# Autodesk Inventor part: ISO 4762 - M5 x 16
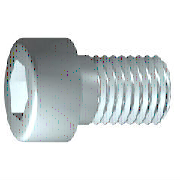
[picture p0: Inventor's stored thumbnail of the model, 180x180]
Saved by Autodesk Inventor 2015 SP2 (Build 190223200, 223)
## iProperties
Created: 2012-02
Part Number: ISO 4762 - M5 x 16
Material: Edelstahl, 440C
Description: Innensechskantschraube
Document SubType Name: Modeling
Standard: ISO 4762
Designer: Dan
Standard Revision: 1998
Standards Organization: DIN
Language: de-DE
Size Designation: M5 x 16
Categories: <MemberInstance><Categories><Category DisplayName="Verbindungselemente" InternalName="e4da775c-781d-43d5-af7c-5136215cf5a6" Mnemonic="FSTN"><Category DisplayNam
Density: 7.75 g/cm^3
Appearance: Halbpoliert
IsCustomPart: 0
Author: Dan
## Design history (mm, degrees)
sketch "Skizze1"
  geometry: L1 (-1.167, 0)-(16, 0); L2 (16, 0)-(16, 2.5); L3 (16, 2.5)-(2, 2.5); L4 (2, 2.5)-(1.509, 2.5); L5 (1.509, 2.5)-(0, 2.5); L6 (0, 2.5)-(0, 4.25); L7 (0, 4.25)-(-5, 4.25); L8 (-5, 4.25)-(-5, 2.309); L9 (-5, 2.309)-(-2.5, 2.309); L10 (-2.5, 2.309)-(-1.167, 0); L11 (-9.2, 0)-(20.2, 0) reference; L12 (0, -0.85)-(0, 5.1) reference; L13 (2, 2.5)-(0, 2.5)
  constraints: 22 end point, 6 parallel, 2 collinear, 2 perpendicular, 1 horizontal, 1 point on line
  dimensions: "d1" = 14 distance from line of L3.end L2 (= GEL); "d2" = 0.49086 distance of L4.end L3.end (computed from GAL); "d3" = 5 distance between parallel lines of L8 L6 (= KOH); "d4" = 2.5 distance of L8.end L9.end (= INTI); "d5" = 60 deg angle of L10 L1; "d6" = 5 diameter of L3 L1 (= GD); "d7" = 5 diameter of L5 L1 (= BDM); "d8" = 4.6188 diameter of L9 L1 (= 1.1547 x SW); "d9" = 8.5 diameter of L7 L1 (= KOD); "d26" = 16 distance between parallel lines of L12 L2 (= NLG)
revolve "Körper" sketch "Skizze1" stored, may be unused: angle "d10" = 90 deg
sketch "Skizze2"
  geometry: L1 (0, -5.95)-(0, 5.95) reference; L2 (-5.95, 0)-(5.95, 0) reference; L3 (2.309, 0)-(1.155, -2); L4 (1.155, -2)-(-1.155, -2); L5 (-1.155, -2)-(-2.309, 0); L6 (-2.309, 0)-(-1.155, 2); L7 (-1.155, 2)-(1.155, 2); L8 (1.155, 2)-(2.309, 0); 2 further points
  constraints: 12 end point, 1 coincident, 1 horizontal alignment, 1 point on line, 12 other
extrude "Loch" join sketch "Skizze2" stored distance "d11" = 10; taper "d12" = 0 deg
workplane "Work Plane1"
fillet "Fillet2" dims "d30" = 0.1 (= R)
body "Solid1"
fillet "Rundung1" dims "d17" = 0.5 (= RR)
feature "Gewinde" dims "d13" = 14 (= GEL), "d14" = 0
chamfer "Fase1" distance "d15" = 0.49076 (= -0.5 x SPD + 0.5 x GD); stored, may be unused: second distance "d16" = 0.49076 (= GUL), angle "d27" = 45 deg
other parameters: "GD" = 5 [user parameter; used in 2 equation terms], "NLG" = 16 [user parameter; used in 1 equation term], "GEL" = 14 [user parameter; used in 2 equation terms], "KOD" = 8.5 [user parameter; used in 1 equation term], "KOH" = 5 [user parameter; used in 1 equation term], "INTI" = 2.5 [user parameter; used in 1 equation term], "GAL" = 0.49076 (= 0.61345 x PTC) [user parameter; used in 1 equation term], "GUL" = 0.49076 (= 0.61345 x PTC) [user parameter; used in 1 equation term], "BDM" = 5 (= NND) [user parameter; used in 1 equation term], "SW" = 4 [user parameter; used in 2 equation terms], "RR" = 0.5 [user parameter; used in 1 equation term], "SPD" = 4.01848 (= NND - 1.2269 x PTC) [user parameter; used in 1 equation term], "d19" = 0, "d28" = 0, "d29" = 0, "R" = 0.1 [user parameter; used in 1 equation term], "TOA" = 30 deg [user parameter], "GD1" = 4.01848 (= THREADDIA - 1.2269 x PTC) [user parameter], "THREADDIA" = 5 [user parameter; used in 1 equation term], "FAWI" = 45 deg [user parameter], "TPU" = 12.5 (computed from PTC) [user parameter], "PTC" = 0.8 [user parameter; used in 5 equation terms], "NND" = 5 [user parameter; used in 2 equation terms], "E0" = 4.62 (= 1.155 x SW) [user parameter]
